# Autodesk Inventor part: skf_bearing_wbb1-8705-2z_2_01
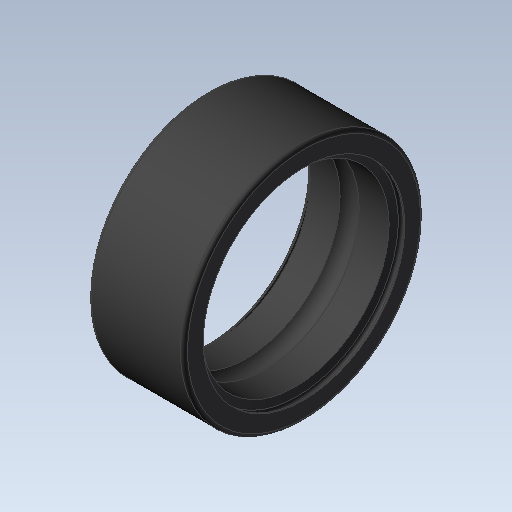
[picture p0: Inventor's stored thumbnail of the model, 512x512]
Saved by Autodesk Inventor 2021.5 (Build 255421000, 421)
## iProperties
Created: 2023-11
Part Number: skf_bearing_wbb1-8705-2z_2_01
Checked By: TraceParts S.A.
Material: Generic
Catalog Web Link: www.traceparts.com
Document SubType Name: Modeling
Designer: TraceParts
Density: 1 g/cm^3
Appearance: Default
Company: TraceParts S.A.
Author: TraceParts
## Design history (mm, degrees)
feature "skf_bearing_wbb1-8705-2z_2_01.ipt"
body "Solid1"
